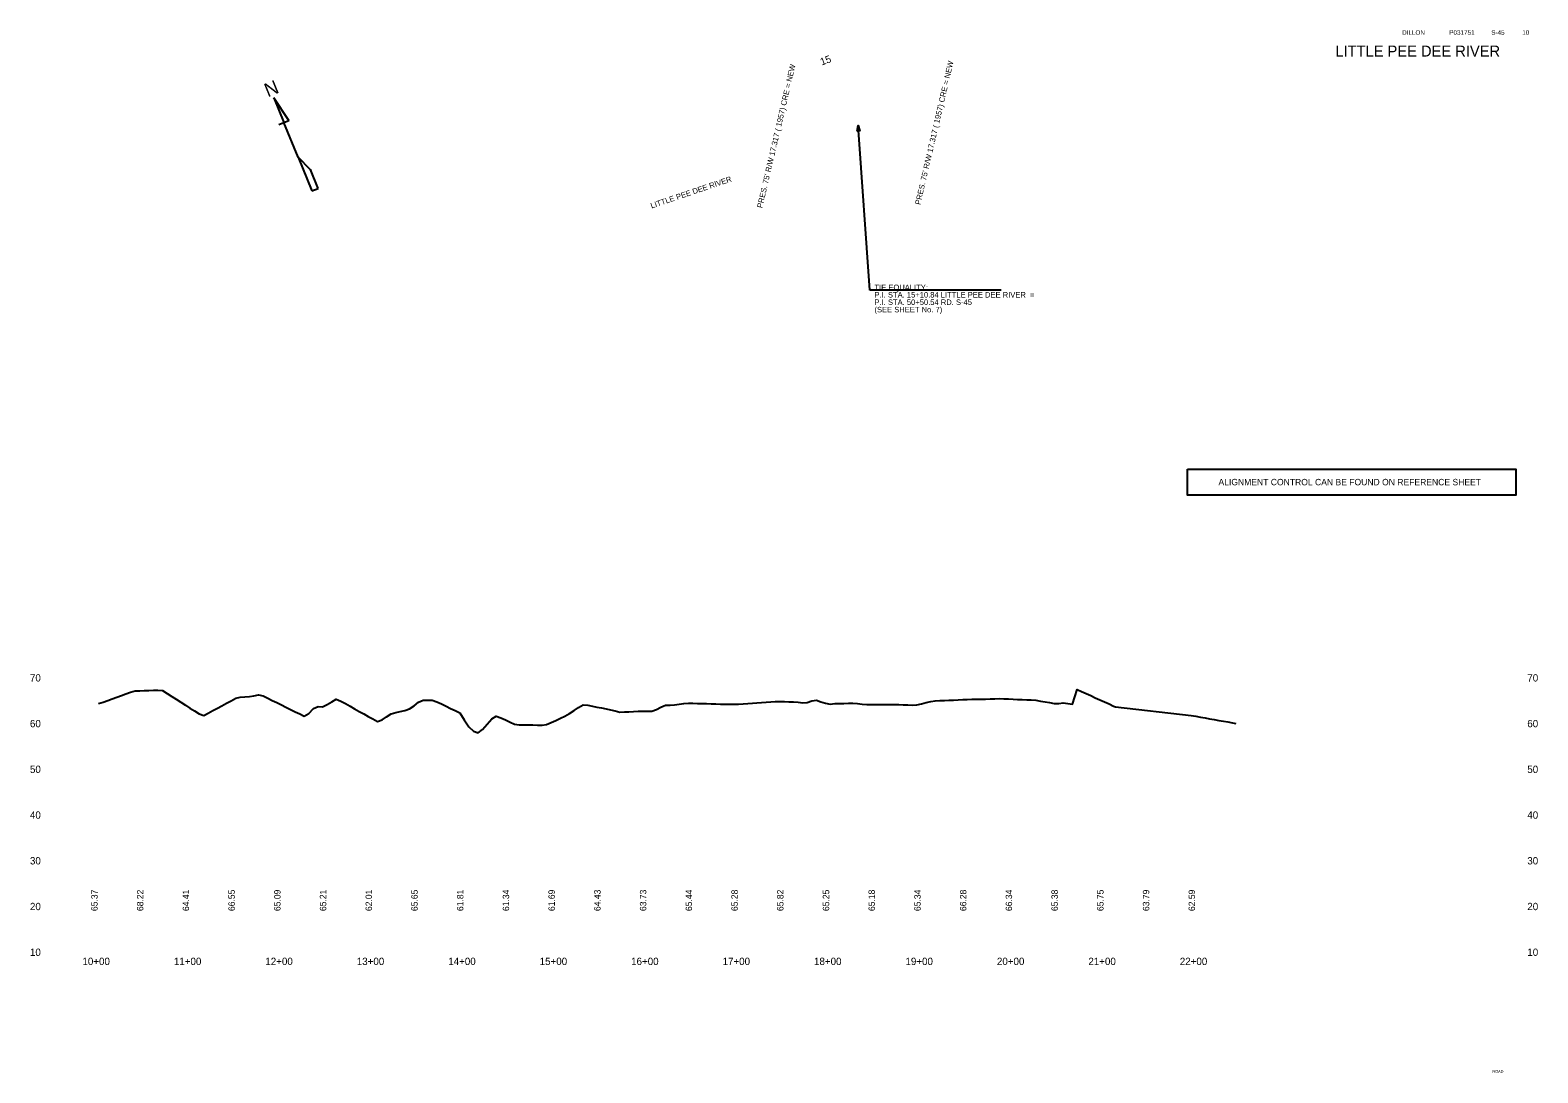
# Model space of a CAD drawing. Extents: x -3336 to 3318, y -3606 to 6276.
# Drawn here: x -75 to 1574, y 3973 to 5113 of the extents above; entities that cross this region are included whole.
import ezdxf

# ---------------------------------------------------------------- set-up
doc = ezdxf.new("R2010")
doc.units = 0
for name, color, linetype in [('RD_DDB_ElevTX', 7, 'Continuous'), ('RD_DDB_Profile_EX', 7, 'Continuous'), ('RD_DDB_StaTX', 7, 'Continuous'), ('RD_DDB_StripGrade', 7, 'Continuous'), ('RD_EX_Misc', 7, 'Continuous'), ('RD_EX_RW_TX', 7, 'Continuous'), ('RD_HC_Data', 7, 'Continuous'), ('RD_HC_TX_Sta50', 7, 'Continuous'), ('RD_SHT_TX', 7, 'Continuous'), ('RD_Sketch1', 7, 'Continuous'), ('RD_TX_Drainage', 7, 'Continuous'), ('RD_TX_RoadID', 7, 'Continuous')]:
    doc.layers.add(name, color=color, linetype=linetype)

msp = doc.modelspace()

# ---------------------------------------------------------------- linework, layer by layer
at = {"layer": 'RD_DDB_Profile_EX'}
for points in [[(0, 4376.9), (5, 4378.6), (10, 4380.4), (15, 4382.1), (20, 4383.9), (25, 4385.7), (30, 4387.4), (35, 4389.2), (40, 4390.8), (45, 4391), (50, 4391.1), (55, 4391.3), (60, 4391.4), (65, 4391.4), (70, 4391.2), (75, 4388), (80, 4384.8), (85, 4381.6), (90, 4378.4), (95, 4375.2), (100, 4372), (105, 4368.8), (110, 4365.7), (115, 4363.8), (120, 4366.5), (125, 4369.2), (130, 4371.9), (135, 4374.6), (140, 4377.3), (145, 4380), (150, 4382.8), (155, 4384), (160, 4384.3), (165, 4384.6), (170, 4385.3), (175, 4386.5), (180, 4385.3), (185, 4382.8), (190, 4380.4), (195, 4377.9), (200, 4375.4), (205, 4373), (210, 4370.5), (215, 4368), (220, 4365.6), (225, 4363.1), (230, 4365.9), (235, 4371.4), (240, 4373.8), (245, 4373.2), (250, 4376), (255, 4378.9), (260, 4381.7), (265, 4379.6), (270, 4376.8), (275, 4374), (280, 4371.2), (285, 4368.4), (290, 4365.6), (295, 4362.9), (300, 4360.1), (305, 4357.3), (310, 4359.1), (315, 4362.3), (320, 4365.5), (325, 4367.1), (330, 4368.2), (335, 4369.3), (340, 4371), (345, 4374.6), (350, 4378.3), (355, 4380.8), (360, 4380.8), (365, 4380.8), (370, 4378.9), (375, 4376.5), (380, 4374.1), (385, 4371.6), (390, 4369.2), (395, 4366.7), (400, 4359), (405, 4351.4), (410, 4346.6), (415, 4344.9), (420, 4348.4), (425, 4354.3), (430, 4360.1), (435, 4363.3), (440, 4361.3), (445, 4359.2), (450, 4356.7), (455, 4354.3), (460, 4353.7), (465, 4353.7), (470, 4353.6), (475, 4353.5), (480, 4353.4), (485, 4353.4), (490, 4353.9), (495, 4356.2), (500, 4358.5)], [(1000, 4381.7), (1005, 4381.5), (1010, 4381.3), (1015, 4381.1), (1020, 4381), (1025, 4380.5), (1030, 4379.7), (1035, 4378.8), (1040, 4378), (1045, 4377), (1050, 4376.9), (1055, 4377.8), (1060, 4376.9), (1065, 4376.1), (1070, 4392.3), (1075, 4390.1), (1080, 4387.8), (1085, 4385.6), (1090, 4383.3), (1095, 4381), (1100, 4378.8), (1105, 4376.5), (1110, 4374.2), (1112.1, 4373.3), (1195, 4363.8), (1200, 4363), (1205, 4362.1), (1210, 4361.2), (1215, 4360.3), (1220, 4359.4), (1225, 4358.5), (1230, 4357.7), (1235, 4356.8), (1240, 4355.9), (1243.8, 4355.2)], [(500, 4358.5), (505, 4360.8), (510, 4363.1), (515, 4366.2), (520, 4369.5), (525, 4372.7), (530, 4375.6), (535, 4375.1), (540, 4374.1), (545, 4373.1), (550, 4372.2), (555, 4371.2), (560, 4370), (565, 4368.8), (570, 4367.5), (575, 4367.8), (580, 4368), (585, 4368.3), (590, 4368.5), (595, 4368.7), (600, 4368.7), (605, 4368.5), (610, 4370.3), (615, 4372.8), (620, 4375), (625, 4375.1), (630, 4375.4), (635, 4376.1), (640, 4376.9), (645, 4377.3), (650, 4377.2), (655, 4377.1), (660, 4376.9), (665, 4376.8), (670, 4376.7), (675, 4376.6), (680, 4376.4), (685, 4376.3), (690, 4376.2), (695, 4376.1), (700, 4376.4), (705, 4376.7), (710, 4377.1), (715, 4377.4), (720, 4377.7), (725, 4378.1), (730, 4378.4), (735, 4378.7), (740, 4379.1), (745, 4379.2), (750, 4379.1), (755, 4378.9), (760, 4378.8), (765, 4378.6), (770, 4377.6), (775, 4378.1), (780, 4380), (785, 4380.6), (790, 4378.9), (795, 4377.2), (800, 4376.2), (805, 4376.8), (810, 4377), (815, 4377.1), (820, 4377.3), (825, 4377.4), (830, 4376.8), (835, 4376.2), (840, 4375.9), (845, 4375.9), (850, 4375.9), (855, 4375.9), (860, 4375.9), (865, 4376), (870, 4376), (875, 4375.8), (880, 4375.6), (885, 4375.4), (890, 4375.2), (895, 4375.5), (900, 4376.7), (905, 4377.9), (910, 4379.1), (915, 4379.9), (920, 4380.1), (925, 4380.4), (930, 4380.6), (935, 4380.8), (940, 4380.9), (945, 4381.2), (950, 4381.4), (955, 4381.6), (960, 4381.8), (965, 4381.7), (970, 4381.7), (975, 4381.9), (980, 4382.2), (985, 4382.3), (990, 4382.1), (995, 4381.9), (1000, 4381.7)]]:
    msp.add_lwpolyline(points, dxfattribs=at)
at = {"layer": 'RD_EX_Misc'}
for p, q in [((208.2, 5014.5), (191.6, 5039.4)), ((191.6, 5039.4), (191.6, 5039.4)), ((191.6, 5039.4), (202.8, 5012.2)), ((197.3, 5010), (202.8, 5012.2)), ((202.8, 5012.2), (208.2, 5014.5)), ((218.2, 4974.5), (202.8, 5012.2)), ((208.2, 5014.5), (208.1, 5014.8)), ((231.8, 4960.6), (218.2, 4974.5)), ((218.2, 4974.5), (233.4, 4937.4)), ((240.2, 4940.2), (231.7, 4960.8)), ((231.7, 4960.8), (231.8, 4960.6)), ((233.4, 4937.4), (240.2, 4940.2))]:
    msp.add_line(p, q, dxfattribs=at)
at = {"layer": 'RD_HC_Data'}
for p, q in [((843.5, 4829), (830.5, 5009)), ((987, 4829), (843.5, 4829))]:
    msp.add_line(p, q, dxfattribs=at)
at = {"layer": 'RD_Sketch1'}
msp.add_lwpolyline([(1190.8, 4633.3), (1550, 4633.3), (1550, 4604.9), (1190.8, 4604.9)], close=True, dxfattribs=at)
at = {"layer": 'RD_TX_Drainage'}
msp.add_lwpolyline([(829.5, 5002.9), (830.5, 5009), (832.5, 5003.1)], close=True, dxfattribs=at)

# ---------------------------------------------------------------- texts
at = {"layer": 'RD_DDB_ElevTX'}
for s, p in [('70', (-75, 4401)), ('70', (1562.4, 4401)), ('60', (-75, 4351)), ('60', (1562.4, 4351)), ('50', (-75, 4301)), ('50', (1562.4, 4301)), ('40', (-75, 4251)), ('40', (1562.4, 4251)), ('30', (-75, 4201)), ('30', (1562.4, 4201)), ('20', (-75, 4151)), ('20', (1562.4, 4151)), ('10', (-75, 4101)), ('10', (1562.4, 4101))]:
    msp.add_text(s, height=8, dxfattribs=at).set_placement(p)
at = {"layer": 'RD_DDB_StaTX'}
for s, p in [('10+00', (-17.6, 4091)), ('11+00', (82.4, 4091)), ('12+00', (182.4, 4091)), ('13+00', (282.4, 4091)), ('14+00', (382.4, 4091)), ('15+00', (482.4, 4091)), ('16+00', (582.4, 4091)), ('17+00', (682.4, 4091)), ('18+00', (782.4, 4091)), ('19+00', (882.4, 4091)), ('20+00', (982.4, 4091)), ('21+00', (1082.4, 4091)), ('22+00', (1182.4, 4091))]:
    msp.add_text(s, height=8, dxfattribs=at).set_placement(p)
at = {"layer": 'RD_DDB_StripGrade'}
for s, p in [('65.37', (-1, 4150)), ('68.22', (49, 4150)), ('64.41', (99, 4150)), ('66.55', (149, 4150)), ('65.09', (199, 4150)), ('65.21', (249, 4150)), ('62.01', (299, 4150)), ('65.65', (349, 4150)), ('61.81', (399, 4150)), ('61.34', (449, 4150)), ('61.69', (499, 4150)), ('64.43', (549, 4150)), ('63.73', (599, 4150)), ('65.44', (649, 4150)), ('65.28', (699, 4150)), ('65.82', (749, 4150)), ('65.25', (799, 4150)), ('65.18', (849, 4150)), ('65.34', (899, 4150)), ('66.28', (949, 4150)), ('66.34', (999, 4150)), ('65.38', (1049, 4150)), ('65.75', (1099, 4150)), ('63.79', (1149, 4150)), ('62.59', (1199, 4150))]:
    msp.add_text(s, height=7, rotation=90, dxfattribs=at).set_placement(p)
at = {"layer": 'RD_EX_Misc'}
msp.add_text('N', height=15, rotation=22.2287, dxfattribs=at).set_placement((185.1, 5039.8))
at = {"layer": 'RD_EX_RW_TX'}
for p in [(725.8, 4918.3), (898.6, 4921.9)]:
    msp.add_text("PRES. 75' R/W 17.317 ( 1957) CRE = NEW", height=6, rotation=76.9375, dxfattribs=at).set_placement(p)
at = {"layer": 'RD_HC_Data'}
for s, p in [('TIE EQUALITY:', (848.5, 4829)), ('P.I. STA. 15+10.84 LITTLE PEE DEE RIVER  =', (848.5, 4820.9)), ('P.I. STA. 50+50.54 RD. S-45 ', (848.5, 4812.8)), ('(SEE SHEET No. 7)', (848.5, 4804.7))]:
    msp.add_text(s, height=6, dxfattribs=at).set_placement(p)
at = {"layer": 'RD_HC_TX_Sta50'}
msp.add_text('15', height=8, rotation=19.7902, dxfattribs=at).set_placement((790.8, 5074.6))
at = {"layer": 'RD_SHT_TX'}
for s, height, p in [('DILLON', 5, (1425.5, 5108.2)), ('P031751', 5, (1477.1, 5108.2)), ('S-45', 5, (1523, 5108.2)), ('10', 5, (1556.9, 5108.2)), ('LITTLE PEE DEE RIVER', 12, (1352.5, 5084.4)), ('ROAD', 3, (1524.3, 3973.1))]:
    msp.add_text(s, height=height, dxfattribs=at).set_placement(p)
at = {"layer": 'RD_Sketch1'}
msp.add_text('ALIGNMENT CONTROL CAN BE FOUND ON REFERENCE SHEET', height=7, dxfattribs=at).set_placement((1224.7, 4615.6))
at = {"layer": 'RD_TX_RoadID'}
msp.add_text('LITTLE PEE DEE RIVER', height=6, rotation=18.6971, dxfattribs=at).set_placement((604.8, 4918.2))

doc.saveas('drawing.dxf')
